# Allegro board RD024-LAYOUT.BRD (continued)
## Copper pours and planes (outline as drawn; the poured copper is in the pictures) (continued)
DC_IN on CONDUCTIVE3: 18.93,68.8 18.86,68.82 18.79,68.86 18.19,69.46 18.16,69.5 18.15,69.56 18.15,69.59 18.04,70.14 17.73,70.61 17.41,70.93 16.89,71.28 16.28,71.4 15.38,71.4 15.31,71.42 15.24,71.46 14.86,71.84 14.82,71.91 14.8,71.98 14.8,77.52 14.82,77.59 14.86,77.66 15.34,78.14 15.38,78.17 15.48,78.2 21.92,78.2 21.97,78.19 22.06,78.14 22.94,77.26 22.97,77.22 23,77.12 23,75.7 23,71 23,69.98 22.99,69.93 22.94,69.84 21.94,68.84 21.9,68.81 21.84,68.8
DC_IN on CONDUCTIVE4: 18.93,68.8 18.88,68.81 18.79,68.86 18.19,69.46 18.16,69.5 18.15,69.56 18.15,69.59 18.04,70.14 17.73,70.61 17.41,70.93 16.89,71.28 16.28,71.4 15.38,71.4 15.31,71.42 15.24,71.46 14.86,71.84 14.82,71.91 14.8,71.98 14.8,77.52 14.82,77.59 14.86,77.66 15.34,78.14 15.38,78.17 15.48,78.2 21.92,78.2 21.97,78.19 22.06,78.14 22.94,77.26 22.97,77.22 23,77.12 23,69.98 22.99,69.93 22.94,69.84 21.94,68.84 21.9,68.81 21.84,68.8
LGND on TOP: outline of 115 points within 41.75,45.3 52.38,74.83
LGND on TOP: outline of 161 points within 41.75,0.5 81.5,81.5 ; 4 cut-outs
LGND on BOTTOM: 42.31,42.12 42.24,42.16 41.81,42.59 41.78,42.63 41.75,42.73 41.75,43.9 41.75,54.32 41.76,54.37 41.81,54.46 42.19,54.84 42.23,54.87 42.33,54.9 43.7,54.9 44.12,55.08 44.3,55.5 44.3,55.76 44.32,55.83 44.37,55.89 44.43,55.93 44.53,56.04 44.57,56.07 44.67,56.1 45.8,56.1 45.85,56.09 45.94,56.04 46.12,55.86 46.15,55.82 46.18,55.72 46.18,53.7 46.18,53.7 46.18,42.76 46.17,42.71 46.12,42.62 45.66,42.16 45.62,42.13 45.52,42.1 42.38,42.1
LGND on BOTTOM: outline of 352 points within 41.75,0.5 81.5,81.5
LGND on CONDUCTIVE2, CONDUCTIVE5: 41.75,80.72 41.77,80.79 41.81,80.86 42.39,81.44 42.46,81.48 42.53,81.5 80,81.5 81.06,81.06 81.5,80 81.5,2 81.06,0.94 80,0.5 42.63,0.5 42.56,0.52 42.49,0.56 41.81,1.24 41.77,1.31 41.75,1.38 41.75,72.99 41.79,73.07 41.89,73.08 42.66,73.6 41.89,74.12 41.79,74.13 41.75,74.21 ; 161 cut-outs
LGND on CONDUCTIVE3: 64.65,46.9 64.52,47.22 64.2,47.35 54.45,47.35 54.38,47.37 54.31,47.41 53.85,47.87 53.83,47.9 53.82,47.94 53.82,58.72 53.82,58.79 53.8,58.89 53.8,59.1 53.74,59.24 53.6,59.3 53.54,59.3 53.5,59.31 53.46,59.34 53.25,59.47 53.02,59.52 47.52,59.52 47.25,59.47 47.02,59.31 46.39,58.68 46.23,58.45 46.18,58.18 46.18,42.68 46.16,42.61 46.12,42.54 45.74,42.16 45.67,42.12 45.6,42.1 42.38,42.1 42.31,42.12 42.24,42.16 41.81,42.59 41.77,42.66 41.75,42.73 41.75,72.99 41.79,73.07 41.89,73.08 42.66,73.6 41.89,74.12 41.79,74.13 41.75,74.21 41.75,80.72 41.77,80.79 41.81,80.86 42.39,81.44 42.46,81.48 42.53,81.5 80,81.5 81.06,81.06 81.5,80 81.5,2 81.06,0.94 80,0.5 42.63,0.5 42.56,0.52 42.49,0.56 41.81,1.24 41.77,1.31 41.75,1.38 41.75,15.15 41.81,15.29 41.95,15.35 64.2,15.35 64.52,15.48 64.65,15.8 64.65,30.1 64.64,30.2 64.6,30.31 64.6,30.33 64.6,30.67 64.64,30.8 64.65,30.9 ; 12 cut-outs
LGND on CONDUCTIVE4: outline of 135 points within 41.75,0.5 81.5,81.5 ; 9 cut-outs
LM5046VCC on TOP (solid shape): 16.84,9 15.9,8.14 15.9,6.46 16.84,5.6 16.84,4.54 15.9,4.54 14.85,5.6 14.85,9 15.9,10.05 16.84,10.05
LM5046VCC on TOP: 15.9,4.54 15.84,4.6 8.82,4.6 8.75,4.61 8.61,4.69 8.09,5.21 8.04,5.27 8,5.42 8,7.58 8.01,7.65 8.09,7.79 9.54,9.24 9.58,9.27 9.68,9.3 15.14,9.3 15.9,10.05 16.84,10.05 16.84,9 15.9,8.14 15.9,6.46 16.84,5.6 16.84,4.54
LM5046VCC on BOTTOM: 9.66,5.79 9.6,5.8 9.56,5.84 9.18,6.21 9.13,6.27 9.09,6.42 9.09,9.87 9.1,9.95 9.18,10.08 10.21,11.11 10.27,11.16 10.42,11.2 17.2,11.2 17.35,11.16 17.46,11.05 17.5,10.9 17.5,10.5 17.41,10.29 17.2,10.2 14.12,10.2 14.01,10.18 13.91,10.11 13.69,9.89 13.62,9.79 13.6,9.68 13.6,8.7 13.51,8.49 13.3,8.4 11.9,8.4 11.75,8.36 11.64,8.25 11.6,8.1 11.6,6.09 11.56,5.94 11.45,5.83 11.3,5.79
PN on TOP: outline of 486 points within 0.5,0.5 39.25,81.5 ; 2 cut-outs
PN on BOTTOM: outline of 357 points within 0.5,0.5 39.25,81.5 ; 3 cut-outs
PN on BOTTOM: outline of 91 points within 25.9,51.9 36.4,65.35
PN on BOTTOM: 31.8,3.3 31.65,3.34 31.54,3.45 31.5,3.6 31.5,7.1 31.54,7.25 31.65,7.36 31.8,7.4 33.3,7.4 33.45,7.36 33.56,7.25 33.6,7.1 33.6,3.6 33.56,3.45 33.45,3.34 33.3,3.3
PN on BOTTOM: 26.98,66.78 26.88,66.8 26.8,66.88 26.77,66.97 26.77,67.2 26.75,67.3 26.68,67.37 26.57,67.4 24.73,67.4 24.63,67.37 24.59,67.34 24.51,67.26 24.47,67.23 24.37,67.2 24.1,67.2 24,67.23 23.93,67.3 23.9,67.4 23.9,67.98 23.92,68.06 23.96,68.12 24.05,68.22 24.09,68.25 24.19,68.27 25.3,68.28 25.71,68.44 25.88,68.85 25.88,69.67 25.88,69.72 25.93,69.81 26.02,69.89 26.06,69.92 26.16,69.95 30.23,69.95 30.28,69.94 30.37,69.89 30.76,69.51 30.79,69.46 30.8,69.4 30.8,69.03 30.76,68.92 30.65,68.88 29.53,68.88 29.49,68.88 29.34,68.96 29.23,68.97 28.93,68.97 28.66,68.87 28.55,68.6 28.55,66.97 28.52,66.88 28.45,66.8 28.35,66.78
PN on CONDUCTIVE2: 0.5,80 0.94,81.06 2,81.5 38.47,81.5 38.54,81.48 38.61,81.44 39.19,80.86 39.23,80.79 39.25,80.72 39.25,72.83 39.21,72.75 39.13,72.73 37.45,71.3 39.13,69.87 39.21,69.85 39.25,69.77 39.25,1.38 39.23,1.31 39.19,1.24 38.51,0.56 38.44,0.52 38.37,0.5 2,0.5 0.94,0.94 0.5,2 ; 47 cut-outs
PN on CONDUCTIVE3: 0.5,80 0.94,81.06 2,81.5 38.47,81.5 38.54,81.48 38.61,81.44 39.19,80.86 39.23,80.79 39.25,80.72 39.25,72.83 39.21,72.75 39.13,72.73 37.45,71.3 39.13,69.87 39.21,69.85 39.25,69.77 39.25,1.38 39.23,1.31 39.19,1.24 38.51,0.56 38.44,0.52 38.37,0.5 2,0.5 0.94,0.94 0.5,2 ; 29 cut-outs
PN on CONDUCTIVE4: outline of 257 points within 0.5,0.5 39.25,81.5 ; 27 cut-outs
PN on CONDUCTIVE5: 0.5,80 0.94,81.06 2,81.5 38.47,81.5 38.54,81.48 38.61,81.44 39.19,80.86 39.23,80.79 39.25,80.72 39.25,72.83 39.21,72.75 39.13,72.73 37.45,71.3 39.13,69.87 39.21,69.85 39.25,69.77 39.25,1.38 39.23,1.31 39.19,1.24 38.51,0.56 38.44,0.52 38.37,0.5 2,0.5 0.94,0.94 0.5,2 ; 47 cut-outs
SEC_1 on TOP: 55.2,27.75 55.24,27.86 55.35,27.9 56.78,27.9 56.89,27.92 56.99,27.99 59.26,30.26 59.3,30.29 59.36,30.3 62.16,30.3 62.22,30.29 62.29,30.23 62.33,30.23 63.67,30.23 63.71,30.23 63.78,30.29 63.84,30.3 64.2,30.3 64.3,30.27 64.37,30.2 64.4,30.1 64.4,19.6 64.31,19.39 64.1,19.3 59.55,19.3 59.48,19.27 59.45,19.2 59.45,14.85 59.41,14.74 59.3,14.7 55.35,14.7 55.24,14.74 55.2,14.85 ; 1 cut-out
SEC_1 on BOTTOM: 41.75,41.08 41.77,41.19 41.84,41.29 42.26,41.71 42.36,41.78 42.47,41.8 45.38,41.8 45.49,41.78 45.59,41.71 46.01,41.29 46.08,41.19 46.1,41.08 46.1,29.98 46.12,29.91 46.16,29.84 48.04,27.96 48.13,27.91 48.18,27.9 56.82,27.9 56.92,27.93 56.96,27.96 59.24,30.24 59.28,30.27 59.38,30.3 64,30.3 64.1,30.27 64.17,30.2 64.2,30.1 64.2,15.8 64.14,15.66 64,15.6 44.27,15.6 44.16,15.62 44.06,15.69 41.79,17.96 41.76,18 41.75,18.06 ; 1 cut-out
SEC_1 on CONDUCTIVE2, CONDUCTIVE5: 61.15,26.35 61.05,26.38 60.98,26.45 60.95,26.55 60.95,29.45 60.98,29.55 61.05,29.62 61.15,29.65 64.05,29.65 64.15,29.62 64.22,29.55 64.25,29.45 64.25,26.55 64.22,26.45 64.15,26.38 64.05,26.35
SEC_1 on CONDUCTIVE2, CONDUCTIVE5: 61.15,19.85 61.05,19.88 60.98,19.95 60.95,20.05 60.95,22.95 60.98,23.05 61.05,23.12 61.15,23.15 64.05,23.15 64.15,23.12 64.22,23.05 64.25,22.95 64.25,20.05 64.22,19.95 64.15,19.88 64.05,19.85
SEC_1 on CONDUCTIVE3, CONDUCTIVE4: 41.75,41.08 41.77,41.19 41.84,41.29 42.26,41.71 42.36,41.78 42.47,41.8 45.38,41.8 45.49,41.78 45.59,41.71 46.01,41.29 46.08,41.19 46.1,41.08 46.1,29.98 46.13,29.88 46.16,29.84 48.04,27.96 48.13,27.91 48.18,27.9 56.78,27.9 56.89,27.92 56.99,27.99 59.26,30.26 59.3,30.29 59.36,30.3 64.2,30.3 64.3,30.27 64.37,30.2 64.4,30.1 64.4,15.8 64.37,15.7 64.3,15.63 64.2,15.6 44.27,15.6 44.2,15.61 44.06,15.69 41.79,17.96 41.76,18 41.75,18.06 ; 1 cut-out
SEC_2 on TOP: 46.75,45.3 46.64,45.34 46.6,45.45 46.6,58.18 46.61,58.25 46.69,58.39 47.31,59.01 47.37,59.06 47.52,59.1 59.18,59.1 59.25,59.09 59.39,59.01 60.11,58.29 60.16,58.23 60.2,58.08 60.2,50.7 60.16,50.55 60.05,50.44 59.9,50.4 54.52,50.4 54.37,50.36 54.31,50.31 53.49,49.49 53.41,49.35 53.4,49.28 53.4,45.45 53.36,45.34 53.25,45.3
SEC_2 on BOTTOM: 47.52,36.7 47.41,36.72 47.31,36.79 46.69,37.41 46.62,37.51 46.6,37.62 46.6,58.18 46.61,58.25 46.69,58.39 47.31,59.01 47.37,59.06 47.52,59.1 53.02,59.1 53.07,59.09 53.16,59.04 53.34,58.86 53.37,58.82 53.4,58.72 53.4,37.66 53.39,37.6 53.36,37.56 52.59,36.79 52.49,36.72 52.38,36.7
SEC_2 on CONDUCTIVE3: 47.52,36.7 47.41,36.72 47.31,36.79 46.69,37.41 46.62,37.51 46.6,37.62 46.6,58.18 46.62,58.29 46.69,58.39 47.31,59.01 47.37,59.06 47.52,59.1 53.02,59.1 53.07,59.09 53.16,59.04 53.34,58.86 53.37,58.82 53.4,58.72 53.4,37.66 53.39,37.6 53.36,37.56 52.59,36.79 52.49,36.72 52.38,36.7
SEC_2 on CONDUCTIVE4: 47.52,36.7 47.41,36.72 47.31,36.79 46.69,37.41 46.62,37.51 46.6,37.62 46.6,58.18 46.61,58.25 46.69,58.39 47.31,59.01 47.37,59.06 47.52,59.1 53.02,59.1 53.07,59.09 53.16,59.04 53.34,58.86 53.37,58.82 53.4,58.72 53.4,37.66 53.39,37.6 53.36,37.56 52.59,36.79 52.49,36.72 52.38,36.7
SEC_3 on TOP: 59,44.05 59.03,43.98 59.1,43.95 62.1,43.95 62.21,43.91 62.25,43.8 62.25,43.3 62.27,43.25 62.33,43.23 64.2,43.23 64.3,43.2 64.37,43.12 64.4,43.02 64.4,32.48 64.37,32.38 64.3,32.3 64.2,32.27 62.33,32.27 62.27,32.25 62.25,32.2 62.25,31.32 62.26,31.25 62.25,31.18 62.25,30.85 62.21,30.74 62.1,30.7 59.12,30.7 59.01,30.68 58.91,30.61 56.69,28.39 56.59,28.32 56.48,28.3 55.35,28.3 55.24,28.34 55.2,28.45 55.2,47.75 55.24,47.86 55.35,47.9 58.85,47.9 58.96,47.86 59,47.75 ; 1 cut-out
SEC_3 on BOTTOM: 61.1,39.42 60.99,39.47 60.95,39.58 60.95,42.4 60.98,42.5 61.05,42.57 61.15,42.6 64,42.6 64.05,42.59 64.1,42.57 64.17,42.5 64.19,42.45 64.2,42.4 64.2,39.62 64.17,39.52 64.1,39.45 64,39.42
SEC_3 on BOTTOM: outline of 87 points within 46.6,28.3 64.4,47.1
SEC_3 on CONDUCTIVE2, CONDUCTIVE5: 61.15,39.35 61.05,39.38 60.98,39.45 60.95,39.55 60.95,42.45 60.98,42.55 61.05,42.62 61.15,42.65 64.05,42.65 64.15,42.62 64.22,42.55 64.25,42.45 64.25,39.55 64.22,39.45 64.15,39.38 64.05,39.35
SEC_3 on CONDUCTIVE2, CONDUCTIVE5: 61.15,32.85 61.05,32.88 60.98,32.95 60.95,33.05 60.95,35.95 60.98,36.05 61.05,36.12 61.15,36.15 64.05,36.15 64.15,36.12 64.22,36.05 64.25,35.95 64.25,33.05 64.22,32.95 64.15,32.88 64.05,32.85
SEC_3 on CONDUCTIVE3: 48.48,28.3 48.43,28.31 48.34,28.36 46.69,30.01 46.64,30.07 46.6,30.22 46.6,35.28 46.62,35.39 46.69,35.49 47.31,36.11 47.41,36.18 47.52,36.2 52.68,36.2 52.79,36.22 52.89,36.29 53.88,37.31 53.9,37.42 53.9,45.88 53.92,45.99 53.99,46.09 54.94,47.04 54.98,47.07 55.08,47.1 64.2,47.1 64.3,47.07 64.37,47 64.4,46.9 64.4,30.9 64.37,30.8 64.3,30.73 64.2,30.7 59.12,30.7 59.01,30.68 58.91,30.61 56.69,28.39 56.59,28.32 56.48,28.3
SEC_3 on CONDUCTIVE4: 48.48,28.3 48.43,28.31 48.34,28.36 46.69,30.01 46.64,30.07 46.6,30.22 46.6,35.28 46.62,35.39 46.69,35.49 47.31,36.11 47.41,36.18 47.52,36.2 52.68,36.2 52.79,36.22 52.89,36.29 53.88,37.31 53.9,37.42 53.9,45.88 53.92,45.99 53.99,46.09 54.99,47.09 55.03,47.12 55.13,47.15 64.2,47.15 64.3,47.12 64.37,47.05 64.4,46.95 64.4,30.9 64.37,30.8 64.3,30.73 64.2,30.7 59.12,30.7 59.01,30.68 58.91,30.61 56.69,28.39 56.59,28.32 56.48,28.3
SIG9 on TOP: 20.45,31.45 20.35,31.48 20.28,31.55 20.25,31.65 20.25,33.05 20.29,33.16 20.4,33.2 20.45,33.2 20.56,33.16 20.6,33.05 20.6,32.5 20.63,32.4 20.7,32.33 20.8,32.3 22.1,32.3 22.2,32.27 22.27,32.2 22.3,32.1 22.3,31.65 22.27,31.55 22.2,31.48 22.1,31.45
SIG12 on TOP: 18.8,18.2 18.7,18.23 18.63,18.3 18.6,18.4 18.6,20.95 18.64,21.06 18.75,21.1 18.8,21.1 18.91,21.06 18.95,20.95 18.95,20.18 18.98,20.08 19.01,20.04 19.36,19.69 19.39,19.65 19.4,19.59 19.4,18.4 19.37,18.3 19.3,18.23 19.2,18.2
SIG16 on TOP: 9.6,18.2 9.5,18.23 9.43,18.3 9.4,18.4 9.4,20.95 9.44,21.06 9.55,21.1 9.6,21.1 9.71,21.06 9.75,20.95 9.75,20.28 9.78,20.18 9.81,20.14 10.16,19.79 10.19,19.75 10.2,19.69 10.2,18.4 10.17,18.3 10.1,18.23 10,18.2
SIG17 on TOP: 6.2,31.45 6.1,31.48 6.03,31.55 6,31.65 6,33.05 6.04,33.16 6.15,33.2 6.2,33.2 6.31,33.16 6.35,33.05 6.35,32.5 6.38,32.4 6.45,32.33 6.55,32.3 7.8,32.3 7.9,32.27 7.97,32.2 8,32.1 8,31.65 7.97,31.55 7.9,31.48 7.8,31.45
SIG22 on TOP: outline of 124 points within 2.6,33.9 25.2,48.8 ; 6 cut-outs
SIG22 on BOTTOM: 4.05,33.9 3.94,33.94 3.9,34.05 3.9,35.75 3.94,35.86 4.05,35.9 6.3,35.9 6.41,35.86 6.45,35.75 6.45,35.66 6.46,35.49 6.5,35.28 6.5,34.12 6.48,34.02 6.43,33.93 6.33,33.9
SIG22 on BOTTOM, CONDUCTIVE2, CONDUCTIVE3, CONDUCTIVE4, CONDUCTIVE5: 18.25,33.9 18.18,33.93 18.15,34 18.15,35.8 18.18,35.87 18.25,35.9 20.65,35.9 20.72,35.87 20.75,35.8 20.75,34 20.72,33.93 20.65,33.9
SIG22 on CONDUCTIVE2, CONDUCTIVE3, CONDUCTIVE4, CONDUCTIVE5: 4,33.9 3.93,33.93 3.9,34 3.9,35.8 3.93,35.87 4,35.9 6.4,35.9 6.47,35.87 6.5,35.8 6.5,34 6.47,33.93 6.4,33.9
SIG37 on TOP: 63.55,44.4 63.44,44.44 63.4,44.55 63.4,47.75 63.44,47.86 63.55,47.9 66.05,47.9 66.16,47.86 66.2,47.75 66.2,44.55 66.16,44.44 66.05,44.4
SIG39 on TOP: 64.05,14.7 63.94,14.74 63.9,14.85 63.9,17.95 63.94,18.06 64.05,18.1 66.55,18.1 66.66,18.06 66.7,17.95 66.7,14.85 66.66,14.74 66.55,14.7
SIG145 on TOP: outline of 133 points within 14.6,15.4 32.88,33.2 ; 3 cut-outs
SIG145 on BOTTOM, CONDUCTIVE2, CONDUCTIVE3, CONDUCTIVE4, CONDUCTIVE5: 16.6,21.8 16.53,21.83 16.5,21.9 16.5,23.7 16.53,23.77 16.6,23.8 19,23.8 19.07,23.77 19.1,23.7 19.1,21.9 19.07,21.83 19,21.8
SIG148 on TOP: outline of 93 points within 2.6,21.8 13.3,33.2 ; 3 cut-outs
SIG148 on BOTTOM: 4.8,21.75 4.7,21.78 4.63,21.85 4.6,21.95 4.6,29.27 4.63,29.38 4.7,29.45 4.8,29.48 11.77,29.48 11.88,29.43 11.92,29.32 11.92,21.97 11.91,21.91 11.88,21.86 11.81,21.79 11.76,21.76 11.7,21.75
SIG148 on CONDUCTIVE3: 30.68,20.86 30.67,20.81 30.62,20.72 29.91,20.01 29.87,19.98 29.77,19.95 3.88,19.95 3.83,19.96 3.74,20.01 2.86,20.89 2.83,20.93 2.8,21.03 2.8,28.02 2.81,28.07 2.86,28.16 3.69,28.99 3.73,29.02 3.83,29.05 29.75,29.05 29.8,29.04 29.89,28.99 30.65,28.23 30.67,28.2 30.68,28.16 ; 1 cut-out
SIG148 on CONDUCTIVE4: 3.88,19.95 3.83,19.96 3.74,20.01 2.86,20.89 2.83,20.93 2.8,21.03 2.8,28.02 2.81,28.07 2.86,28.16 3.69,28.99 3.73,29.02 3.83,29.05 29.75,29.05 29.8,29.04 29.89,28.99 30.65,28.23 30.67,28.2 30.68,28.16 30.68,20.86 30.67,20.81 30.62,20.72 29.91,20.01 29.87,19.98 29.77,19.95 ; 1 cut-out
SIG148 on CONDUCTIVE5: 7.4,21.8 7.33,21.83 7.3,21.9 7.3,23.7 7.33,23.77 7.4,23.8 9.8,23.8 9.87,23.77 9.9,23.7 9.9,21.9 9.87,21.83 9.8,21.8
SIG161 on BOTTOM: 16.85,3.67 16.85,5.15 16.43,5.15 16.43,5.66 16.41,5.73 16.4,5.8 16.4,8.38 16.42,8.49 16.49,8.59 16.71,8.81 16.81,8.88 16.92,8.9 27.32,8.9 27.37,8.89 27.46,8.84 27.74,8.56 27.77,8.52 27.8,8.42 27.8,6.75 27.76,6.64 27.65,6.6 19.28,6.6 19.18,6.57 19.14,6.54 18.19,5.59 18.17,5.57 18.17,5.15 17.75,5.15 17.75,3.67
SIG162 on TOP (solid shape): 20.36,9 20.36,5.6 19.3,4.54 18.36,4.54 18.36,5.6 19.3,6.46 19.3,8.14 18.36,9 18.36,10.05 19.3,10.05
SIG162 on TOP: 36.81,8.59 36.86,8.53 36.9,8.38 36.9,4.6 36.86,4.45 36.75,4.34 36.6,4.3 34.7,4.3 34.62,4.31 34.49,4.39 33.79,5.09 33.65,5.16 33.58,5.17 19.93,5.17 19.3,4.54 18.36,4.54 18.36,5.6 19.3,6.46 19.3,8.14 18.36,9 18.36,10.05 19.3,10.05 19.36,10 35.34,10 35.4,9.99 35.44,9.96 ; 2 cut-outs
SIG162 on BOTTOM: 34.8,3.3 34.65,3.34 34.54,3.45 34.5,3.6 34.5,7.1 34.54,7.25 34.65,7.36 34.8,7.4 36.02,7.4 36.07,7.39 36.16,7.34 36.54,6.96 36.57,6.92 36.6,6.82 36.6,3.78 36.59,3.73 36.54,3.64 36.26,3.36 36.22,3.33 36.12,3.3
SIG165 on BOTTOM: 29.38,3.3 29.33,3.31 29.24,3.36 28.56,4.04 28.53,4.08 28.5,4.18 28.5,7.1 28.54,7.25 28.65,7.36 28.8,7.4 30.4,7.4 30.55,7.36 30.66,7.25 30.7,7.1 30.7,3.5 30.64,3.36 30.5,3.3
SIG168 on BOTTOM: 12.9,3.7 12.75,3.74 12.64,3.85 12.6,4 12.6,6.2 12.64,6.35 12.75,6.46 12.9,6.5 14.6,6.5 14.75,6.46 14.86,6.35 14.9,6.2 14.9,5.2 14.94,5.05 15.05,4.94 15.2,4.9 16.05,4.9 16.16,4.86 16.2,4.75 16.2,4 16.16,3.85 16.05,3.74 15.9,3.7

Small or netless copper shapes (teardrops, artwork), in the pictures only: 4 on TOP, 1 on BOTTOM, 1 on CONDUCTIVE2
